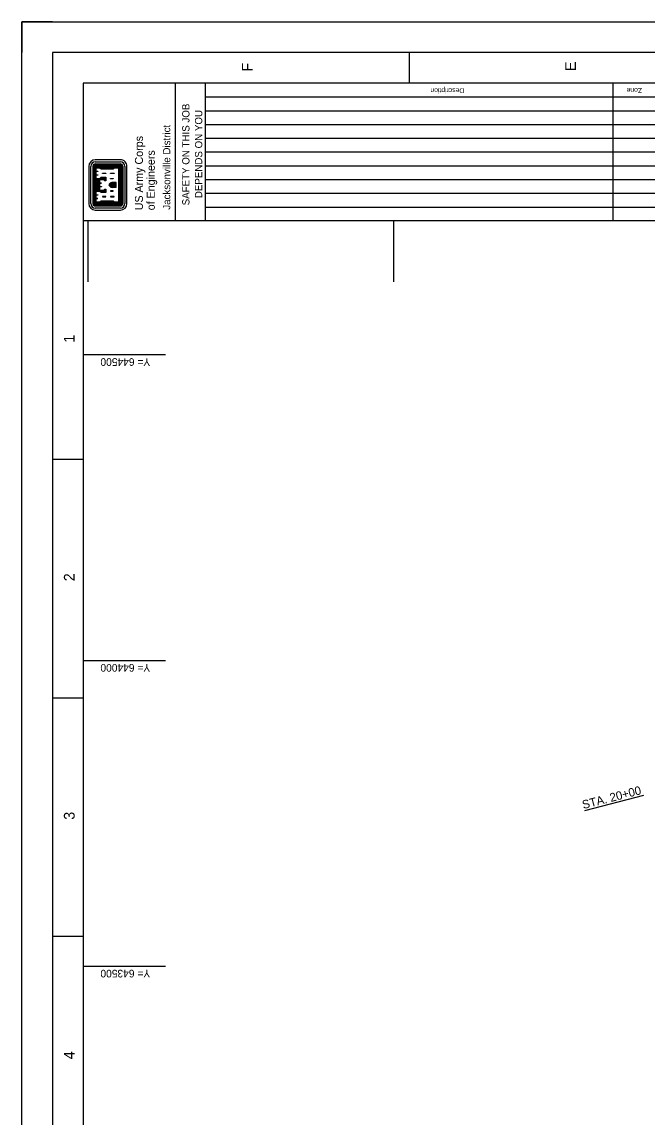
# Model space of a CAD drawing. Extents: x 943892 to 947291, y 640645 to 645045.
# Drawn here: x 943892 to 944914, y 643254 to 645045 of the extents above; entities that cross this region are included whole.
import ezdxf

# ---------------------------------------------------------------- set-up
doc = ezdxf.new("R2010")
doc.units = 0
for name, color, linetype in [('G-ANNO-NPLT', 7, 'Continuous'), ('G-ANNO-TEXT-LOGO', 7, 'Continuous'), ('G-ANNO-TEXT-TTLB', 7, 'Continuous'), ('G-ANNO-TTLB', 7, 'Continuous'), ('V-ALGN-TEXT', 7, 'Continuous'), ('V-TOPO-COOR-STAT', 7, 'Continuous')]:
    doc.layers.add(name, color=color, linetype=linetype)

msp = doc.modelspace()

# ---------------------------------------------------------------- linework, layer by layer
at = {"layer": 'G-ANNO-NPLT'}
msp.add_lwpolyline([(943891.5, 640644.6), (943891.5, 645044.6), (947291.5, 645044.6), (947291.5, 640644.6)], close=True, dxfattribs=at)
msp.add_lwpolyline([(943941.5, 645044.6), (943891.5, 645044.6), (943891.5, 644994.6)], dxfattribs=at)
at = {"layer": 'G-ANNO-TEXT-LOGO'}
for p, q in [((944052.6, 644819.1), (944011.6, 644819.1)), ((944000.9, 644808.4), (944000.9, 644747.6)), ((944004.1, 644747.6), (944004.1, 644808.4)), ((944007.5, 644808.4), (944007.5, 644747.6)), ((944008.4, 644808.4), (944008.4, 644747.6)), ((944009.3, 644808.4), (944009.3, 644747.6)), ((944010.1, 644808.4), (944010.1, 644747.6)), ((944011, 644808.4), (944011, 644747.6)), ((944011.6, 644815.8), (944052.6, 644815.8)), ((944011.6, 644812.4), (944052.6, 644812.4)), ((944011.6, 644811.5), (944052.6, 644811.5)), ((944011.6, 644810.6), (944052.6, 644810.6)), ((944011.6, 644809.8), (944052.6, 644809.8)), ((944011.6, 644808.9), (944052.6, 644808.9)), ((944011.6, 644808), (944052.3, 644808)), ((944011.6, 644807.2), (944051.4, 644807.2)), ((944020.4, 644806.5), (944041.2, 644806.5)), ((944021.2, 644805.6), (944040.3, 644805.6)), ((944051.4, 644807.2), (944051.4, 644748.8)), ((944052.3, 644808), (944052.3, 644748)), ((944053.2, 644808.4), (944053.2, 644747.6)), ((944054, 644808.4), (944054, 644747.6)), ((944054.9, 644808.4), (944054.9, 644747.6)), ((944055.8, 644808.4), (944055.8, 644747.6)), ((944056.6, 644808.4), (944056.6, 644747.6)), ((944060.1, 644808.4), (944060.1, 644747.6)), ((944063.4, 644747.6), (944063.4, 644808.4)), ((944011.8, 644768.7), (944011.8, 644787.3)), ((944012.7, 644768.7), (944012.7, 644787.3)), ((944013.5, 644768.7), (944013.5, 644787.3)), ((944014.4, 644768.7), (944014.4, 644787.3)), ((944015.3, 644768.7), (944015.3, 644787.3)), ((944016.1, 644768.7), (944016.1, 644787.3)), ((944017, 644768.7), (944017, 644787.3)), ((944045.5, 644782), (944038.8, 644782)), ((944045.5, 644781.2), (944038.8, 644781.2)), ((944045.5, 644780.3), (944038.8, 644780.3)), ((944045.5, 644779.4), (944038.8, 644779.4)), ((944045.5, 644778.6), (944038.8, 644778.6)), ((944045.5, 644777.4), (944038.8, 644777.4)), ((944045.5, 644776.6), (944038.8, 644776.6)), ((944045.5, 644775.7), (944038.8, 644775.7)), ((944045.5, 644774.8), (944038.8, 644774.8)), ((944045.5, 644774), (944038.8, 644774)), ((944045.5, 644774), (944045.5, 644782)), ((944011.6, 644748.8), (944051.4, 644748.8)), ((944011.6, 644748), (944052.3, 644748)), ((944011.6, 644747.1), (944052.6, 644747.1)), ((944020.3, 644749.5), (944041.3, 644749.5)), ((944021.2, 644750.4), (944040.3, 644750.4)), ((944011.6, 644746.2), (944052.6, 644746.2)), ((944011.6, 644745.3), (944052.6, 644745.3)), ((944011.6, 644744.5), (944052.6, 644744.5)), ((944011.6, 644743.6), (944052.6, 644743.6)), ((944052.6, 644740.1), (944011.6, 644740.1)), ((944011.6, 644736.9), (944052.6, 644736.9))]:
    msp.add_line(p, q, dxfattribs=at)
for points in [[(944011.6, 644749.5), (944019.5, 644749.5), (944021.2, 644751.2), (944040.3, 644751.2), (944042.1, 644749.5), (944050.8, 644749.5), (944050.8, 644806.5), (944042.1, 644806.5), (944040.3, 644804.7), (944021.2, 644804.7), (944019.5, 644806.5), (944011.6, 644806.5), (944011.6, 644799), (944011.6, 644793.2), (944011.6, 644787.8), (944019.5, 644787.8), (944021.2, 644789.7), (944028.2, 644789.7), (944028.2, 644785.5), (944027.5, 644785.5), (944025.7, 644787.3), (944017.9, 644787.3), (944017.9, 644779.8), (944017.9, 644774), (944017.9, 644768.7), (944025.7, 644768.7), (944027.5, 644770.5), (944028.2, 644770.5), (944028.2, 644766.3), (944021.2, 644766.3), (944019.5, 644768.1), (944011.6, 644768.1), (944011.6, 644760.6), (944011.6, 644754.8), (944011.6, 644749.5)], [(944012.5, 644750.3), (944019.1, 644750.3), (944020.9, 644752.1), (944040.7, 644752.1), (944042.5, 644750.3), (944049.9, 644750.3), (944049.9, 644805.7), (944042.5, 644805.7), (944040.7, 644803.8), (944020.9, 644803.8), (944019.1, 644805.7), (944012.5, 644805.7), (944012.5, 644800.3), (944015.6, 644800.3), (944015.6, 644799.8), (944012.5, 644799.8), (944012.5, 644794.5), (944015.6, 644794.5), (944015.6, 644794.1), (944012.5, 644794.1), (944012.5, 644788.7), (944019.1, 644788.7), (944020.9, 644790.5), (944029, 644790.5), (944029, 644784.7), (944027.1, 644784.7), (944025.3, 644786.5), (944018.7, 644786.5), (944018.7, 644781.1), (944021.8, 644781.1), (944021.8, 644780.7), (944018.7, 644780.7), (944018.7, 644775.3), (944021.8, 644775.3), (944021.8, 644774.8), (944018.7, 644774.8), (944018.7, 644769.5), (944025.3, 644769.5), (944027.1, 644771.3), (944029, 644771.3), (944029, 644765.5), (944020.9, 644765.5), (944019.1, 644767.3), (944012.5, 644767.3), (944012.5, 644762), (944015.6, 644762), (944015.6, 644761.5), (944012.5, 644761.5), (944012.5, 644756.1), (944015.6, 644756.1), (944015.6, 644755.7), (944012.5, 644755.7), (944012.5, 644750.3)], [(944021.1, 644788.3), (944021.6, 644788.8), (944027.3, 644788.8), (944027.3, 644787), (944026, 644788.2), (944021, 644788.2)], [(944023.2, 644797.4), (944029, 644797.4), (944029, 644796.9), (944023.2, 644796.9), (944023.2, 644797.4)], [(944036.5, 644797.4), (944042.4, 644797.4), (944042.4, 644796.9), (944036.5, 644796.9), (944036.5, 644797.4)], [(944036.5, 644788.3), (944040.6, 644788.3), (944040.6, 644787.8), (944036.5, 644787.8), (944036.5, 644788.3)], [(944021.1, 644767.7), (944021.6, 644767.2), (944027.3, 644767.2), (944027.3, 644769.1), (944026, 644767.8), (944021, 644767.8)], [(944036.5, 644767.7), (944040.6, 644767.7), (944040.6, 644768.2), (944036.5, 644768.2), (944036.5, 644767.7)], [(944023.2, 644758.5), (944029, 644758.5), (944029, 644759.1), (944023.2, 644759.1), (944023.2, 644758.5)], [(944036.5, 644758.5), (944042.4, 644758.5), (944042.4, 644759.1), (944036.5, 644759.1), (944036.5, 644758.5)]]:
    msp.add_lwpolyline(points, dxfattribs=at)
for centre, major_axis, start_param, end_param in [((944011.6, 644808.4), (0, 10.7), 6.283169, 7.853965), ((944052.6, 644808.4), (0, 10.7), 4.712373, 6.28317), ((944011.6, 644808.4), (0, 7.49), 6.28317, 7.853966), ((944011.6, 644808.4), (0, 4.02), 6.283169, 7.853965), ((944011.6, 644808.4), (0, 3.15), 6.283169, 7.853965), ((944011.6, 644808.4), (0, 2.28), 6.283169, 7.853965), ((944011.6, 644808.4), (0, 1.41), 6.283169, 7.853965), ((944011.6, 644808.4), (0, 0.546), 6.283169, 7.853965), ((944052.6, 644808.4), (0, -7.49), 1.570781, 3.141577), ((944052.6, 644808.4), (0, 4.02), 4.712373, 6.28317), ((944052.6, 644808.4), (0, 3.15), 4.712373, 6.28317), ((944052.6, 644808.4), (0, 2.28), 4.712373, 6.28317), ((944052.6, 644808.4), (0, 1.41), 4.712373, 6.28317), ((944052.6, 644808.4), (0, 0.546), 4.712373, 6.28317), ((944039.3, 644776.5), (0, 5.55), 0.068795, 1.29842), ((944039.3, 644779.5), (0, -5.55), 4.985832, 6.214359), ((944039.3, 644776.5), (0, 4.69), 0.068795, 1.335689), ((944039.3, 644779.5), (0, -4.69), 4.947465, 6.21436), ((944039.3, 644776.5), (0, 3.82), 0.068795, 1.335689), ((944039.3, 644779.5), (0, -3.82), 4.947465, 6.21436), ((944039.3, 644776.5), (0, 2.95), 0.068794, 1.335689), ((944039.3, 644779.5), (0, -2.95), 4.947465, 6.21436), ((944039.3, 644779.5), (0, -2.08), 4.947465, 6.214359), ((944039.3, 644776.5), (0, 2.08), 0.068794, 1.335689), ((944011.6, 644747.7), (0, 10.7), 1.57078, 3.141576), ((944011.6, 644747.7), (0, 7.49), 1.57078, 3.141576), ((944011.6, 644747.7), (0, 4.02), 1.57078, 3.141576), ((944011.6, 644747.7), (0, 3.15), 1.57078, 3.141576), ((944011.6, 644747.7), (0, 2.28), 1.57078, 3.141576), ((944011.6, 644747.7), (0, 1.41), 1.57078, 3.141576), ((944011.6, 644747.7), (0, 0.546), 1.57078, 3.141576), ((944052.6, 644747.7), (0, -4.02), 6.28317, 7.853966), ((944052.6, 644747.7), (0, -3.15), 6.28317, 7.853966), ((944052.6, 644747.7), (0, -2.28), 6.28317, 7.853966), ((944052.6, 644747.7), (0, -1.41), 6.28317, 7.853966), ((944052.6, 644747.7), (0, -0.546), 6.28317, 7.853966), ((944052.6, 644747.7), (0, -10.7), 6.28317, 7.853966), ((944052.6, 644747.7), (0, -7.49), 6.28317, 7.853966)]:
    msp.add_ellipse(centre, major_axis=major_axis, ratio=0.99964, start_param=start_param, end_param=end_param, dxfattribs=at)
at = {"layer": 'G-ANNO-TTLB'}
for p, q in [((944525, 644994.6), (944525, 644944.6)), ((944142.7, 644719.6), (944142.7, 644944.6)), ((944191.9, 644719), (944191.9, 644944)), ((944858.8, 644719.6), (944858.8, 644944.6)), ((944191.9, 644921.9), (945029.8, 644921.9)), ((944191.9, 644899.4), (945029.8, 644899.4)), ((944191.9, 644876.9), (945029.8, 644876.9)), ((944191.9, 644854.4), (945029.8, 644854.4)), ((944191.9, 644831.9), (945029.8, 644831.9)), ((944191.9, 644809.4), (945029.8, 644809.4)), ((944191.9, 644786.9), (945029.8, 644786.9)), ((944191.9, 644764.4), (945029.8, 644764.4)), ((944191.9, 644741.9), (945029.8, 644741.9)), ((943991.5, 644719.6), (947191.5, 644719.6)), ((943941.5, 644329.6), (943991.5, 644329.6)), ((943941.5, 643939.6), (943991.5, 643939.6)), ((943941.5, 643549.6), (943991.5, 643549.6))]:
    msp.add_line(p, q, dxfattribs=at)
for points in [[(947241.5, 640694.6), (947241.5, 644994.6), (943941.5, 644994.6), (943941.5, 640694.6)], [(943991.5, 644944.6), (943991.5, 640819.6), (947191.5, 640819.6), (947191.5, 644944.6)]]:
    msp.add_lwpolyline(points, close=True, dxfattribs=at)
at = {"layer": 'V-ALGN-TEXT'}
msp.add_line((944812.2, 643755.1), (944909, 643780), dxfattribs=at)
at = {"layer": 'V-TOPO-COOR-STAT'}
for p, q in [((944000, 644619.6), (944000, 644719.6)), ((944500, 644619.6), (944500, 644719.6)), ((944126.5, 644500), (943991.5, 644500)), ((944126.5, 644000), (943991.5, 644000)), ((944126.5, 643500), (943991.5, 643500))]:
    msp.add_line(p, q, dxfattribs=at)

# ---------------------------------------------------------------- texts
at = {"layer": 'G-ANNO-TEXT-TTLB'}
for s, height, rotation, p in [('Description', 8, 180, (944615, 644936.2)), ('Zone', 8, 180, (944905.8, 644936.5)), ('SAFETY ON THIS JOB', 11.9, 90, (944165.6, 644744.7)), ('DEPENDS ON YOU', 11.9, 90, (944186.5, 644756.4)), ('Jacksonville District', 11.9, 90, (944134.2, 644737.5)), ('US Army Corps', 13.086, 90, (944089.5, 644736.5)), ('of Engineers', 13.086, 90, (944108.9, 644736.5))]:
    msp.add_text(s, height=height, rotation=rotation, dxfattribs=at).set_placement(p)
at = {"layer": 'G-ANNO-TTLB'}
for s, p in [('F', (944268.8, 644963.4)), ('E', (944797.7, 644964.2)), ('1', (943977.7, 644520)), ('2', (943977.7, 644130)), ('3', (943977.7, 643740)), ('4', (943977.7, 643348.3))]:
    msp.add_text(s, height=17.5, rotation=90, dxfattribs=at).set_placement(p)
at = {"layer": 'V-ALGN-TEXT'}
msp.add_text('STA. 20+00', height=13.92, rotation=14.4313, dxfattribs=at).set_placement((944809.9, 643757.4))
at = {"layer": 'V-TOPO-COOR-STAT'}
for s, p in [('Y= 644500', (944101.3, 644494.7)), ('Y= 644000', (944101.3, 643994.7)), ('Y= 643500', (944101.3, 643494.7))]:
    msp.add_text(s, height=12.5, rotation=180, dxfattribs=at).set_placement(p)

doc.saveas('drawing.dxf')
